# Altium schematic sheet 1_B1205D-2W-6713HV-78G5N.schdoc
size 289 x 200 mm; Name: default297x210; Symbol: default297x210; Device: default297x210; Date: 2025.06.26; Rev: V1.1; Size: "A4"; Id: /; File: B1205D-2W-6713HV-78G5N; Sheet: /; @Page No: 1; @Page Count: 1; @Schematic Name: B1205D-2W-6713HV-78G5N; @Project Name: 全桥隔离电源-B1205D-2W-6713HV-78G5N; @Board Name: B1205D-2W-6713HV-78G5N; @Update Date: 2025-06-26; @Create Time: 15:50:36; @Update Time: 15:52:41; @Page Name: B1205D-2W-6713HV-78G5N; @Create Date: 2025-06-26
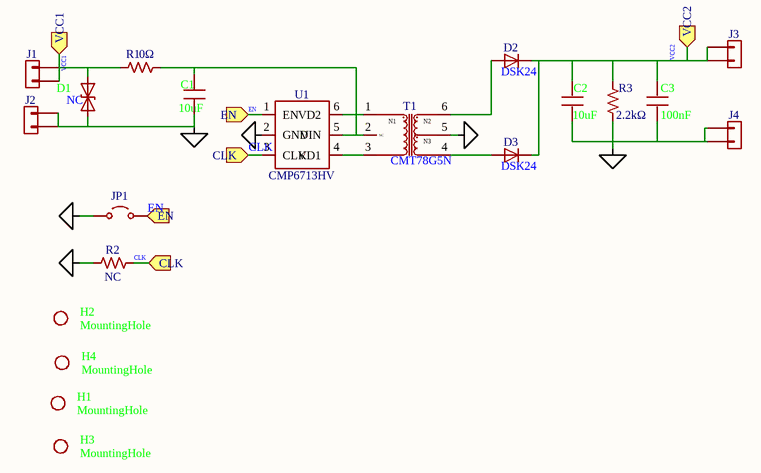
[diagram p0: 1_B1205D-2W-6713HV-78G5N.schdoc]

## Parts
C1  10uF  [C0805]
C2  10uF  [C0805]
C3  100nF  [C0603]
D1  value NC  [SOD-123FL_L2.8-W1.8-LS3.7-BI]
D2  DSK24  [SOD-123_L2.8-W1.8-LS3.7-RD]
D3  DSK24  [SOD-123_L2.8-W1.8-LS3.7-RD]
H1  value MountingHole  [MountingHole:MountingHole_3.2mm_M3]  (hidden comment: Mechanical_MountingHole)
H2  value MountingHole  [MountingHole:MountingHole_3.2mm_M3]  (hidden comment: Mechanical_MountingHole)
H3  value MountingHole  [MountingHole:MountingHole_3.2mm_M3]  (hidden comment: Mechanical_MountingHole)
H4  value MountingHole  [MountingHole:MountingHole_3.2mm_M3]  (hidden comment: Mechanical_MountingHole)
J1  Connector_Generic_Conn_01x02  [Connector_PinHeader_2.54mm:PinHeader_1x02_P2.54mm_Vertical]  (value not drawn)
J2  Connector_Generic_Conn_01x02  [Connector_PinHeader_2.54mm:PinHeader_1x02_P2.54mm_Vertical]  (value not drawn)
J3  Connector_Generic_Conn_01x02  [Connector_PinHeader_2.54mm:PinHeader_1x02_P2.54mm_Vertical]  (value not drawn)
J4  Connector_Generic_Conn_01x02  [Connector_PinHeader_2.54mm:PinHeader_1x02_P2.54mm_Vertical]  (value not drawn)
JP1  Jumper_Jumper_2_Open  [Connector_PinHeader_2.54mm:PinHeader_1x02_P2.54mm_Vertical]  (value not drawn)
R1  0Ω  [R0603]
R2  NC  [R0603]
R3  2.2kΩ  [R0603]
T1  CMT78G5N  [SMD-6_L9.7-W8.9-P2.54-LS12.8-TL]
U1  CMP6713HV  [Package_TO_SOT_SMD:TSOT-23-6]

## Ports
CLK (in), EN (in), VCC1 (in), VCC2 (in)

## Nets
GND1: C1.1 D1.2 J2.1 J2.2 JP1.1 R2.1 U1.2(GND)
GND2: C2.1 C3.1 J4.1 J4.2 R3.2 T1.5
CLK: R2.2 U1.3(CLK) ; port CLK
EN: JP1.2 U1.1(EN) ; port EN
VCC1: D1.1 J1.1 J1.2 R1.1 ; port VCC1
VCC2: C2.2 C3.2 D2.1 D3.1 J3.1 J3.2 R3.1 ; port VCC2
NetC1_2: C1.2 R1.2 T1.2 U1.5(VIN)
NetD2_2: D2.2 T1.6
NetD3_2: D3.2 T1.4
NetT1_1: T1.1 U1.6(VD2)
NetT1_3: T1.3 U1.4(VD1)

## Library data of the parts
C1 = CC0805KKX5R8BB106_C89831: Manufacturer: YAGEO(国巨); Symbol: My_Library_C; Add into BOM: yes; Tolerance: ±10%; Voltage Rated: 25V; Temperature Coefficient: X5R
C2 = CC0805KKX5R6BB106: Manufacturer: YAGEO(国巨); Symbol: My_Library_C; Add into BOM: yes; Tolerance: ±10%; Voltage Rated: 10V; Temperature Coefficient: X5R
C3 = CC0603KRX7R9BB104: Manufacturer: YAGEO(国巨); Symbol: My_Library_C; Add into BOM: yes; Tolerance: ±10%; Voltage Rating: 50V; Temperature Coefficient: X7R
D1 = SMF28CA_C364280: Symbol: Diode_SMAJ30CA; Add into BOM: yes; Type: TVS
D2 D3 = DSK24 K24: Manufacturer: MDD(辰达半导体); Symbol: My_Library_D; Add into BOM: yes; Diode Configuration: 独立式; Forward Voltage (Vf@If): 550mV@2A; Reverse Voltage (Vr): 40V; Rectified Current: 2A; Reverse Leakage Current (Ir): 500uA@40V
H1-H4 = Mechanical_MountingHole: Users: REF**; ki_fp_filters: MountingHole*; Add into BOM: yes
J1-J4 = Connector_Generic_Conn_01x02: Users: REF**; ki_fp_filters: Jumper* TestPoint*2Pads* TestPoint*Bridge*; Add into BOM: yes
JP1 = Jumper_Jumper_2_Open: Add into BOM: yes
R1 = RC0603FR-070RL: Manufacturer: YAGEO(国巨); Symbol: My_Library_R; Add into BOM: yes; Tolerance: ±1%; Power(Watts): 100mW; Voltage-Supply(Max): 75V
R2 = RC0603FR-0715KL: Symbol: My_Library_R; Add into BOM: yes; Tolerance: ±1%
R3 = RC0603FR-072K2L: Manufacturer: YAGEO(国巨); Symbol: My_Library_R; Add into BOM: yes; Tolerance: ±1%; Power(Watts): 100mW; Voltage-Supply(Max): 75V; Temperature Coefficient: ±100ppm/℃
T1 = CMT78G5N: Manufacturer: coileasy(线易); Symbol: My_Library_VPT85BB-02A; Add into BOM: yes
U1 = CMP6713HV: Manufacturer: coileasy(线易); Symbol: MYLibrary_CMP6713RE/HV; Add into BOM: yes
